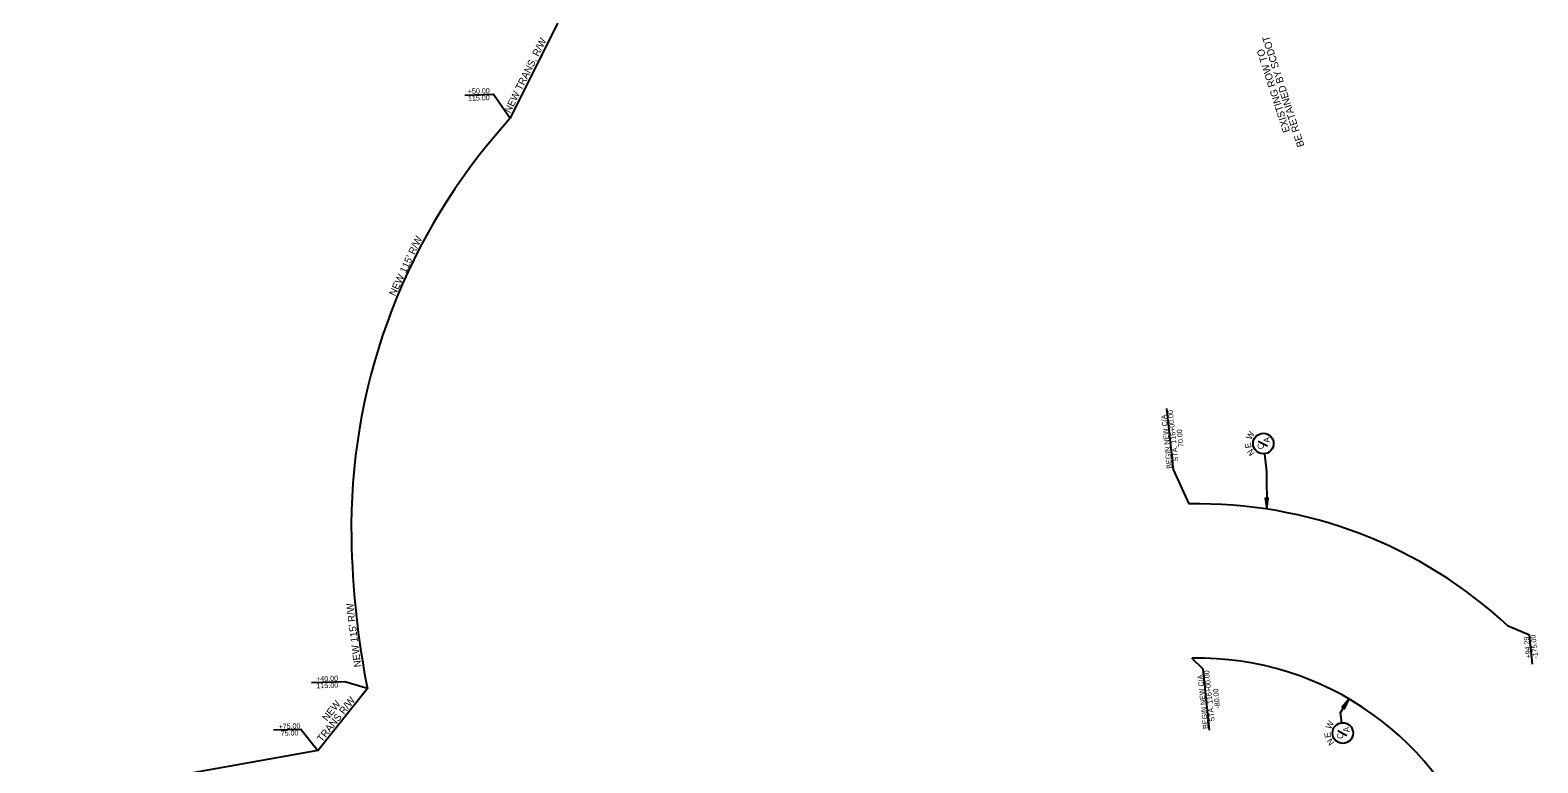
# Model space of a CAD drawing. Extents: x 2003184 to 2010449, y 855784 to 861212.
# Drawn here: x 2003206 to 2004672, y 858179 to 858891 of the extents above; entities that cross this region are included whole.
import ezdxf

# ---------------------------------------------------------------- set-up
doc = ezdxf.new("R2010")
doc.units = 0
for name, color, linetype in [('RD_PD_Control_Access', 7, 'Continuous'), ('RD_PD_RW', 7, 'Continuous'), ('RD_PD_RW_TX', 7, 'Continuous')]:
    doc.layers.add(name, color=color, linetype=linetype)

msp = doc.modelspace()

# ---------------------------------------------------------------- linework, layer by layer
at = {"layer": 'RD_PD_Control_Access'}
for p, q in [((2004399.8, 858491.4), (2004408.7, 858486.7)), ((2004477.1, 858210), (2004486, 858205.3))]:
    msp.add_line(p, q, dxfattribs=at)
for points in [[(2004405.9, 858479), (2004407.7, 858461.5), (2004408, 858425.3)], [(2004481, 858217.5), (2004479.9, 858227.7), (2004488.1, 858240.8)]]:
    msp.add_lwpolyline(points, dxfattribs=at)
for points in [[(2004408, 858425.3), (2004409.4, 858435.7), (2004407.9, 858434.1), (2004406.4, 858435.7)], [(2004488.1, 858240.8), (2004481.3, 858232.7), (2004483.4, 858233.3), (2004483.8, 858231.2)]]:
    msp.add_lwpolyline(points, close=True, dxfattribs=at)
for centre in [(2004404.8, 858488.9), (2004482, 858207.6)]:
    msp.add_circle(centre, 10, dxfattribs=at)
for radius, start in [(441, 46.9147), (291, 17.9087)]:
    msp.add_arc((2004341.6, 857989.3), radius, start, 91.2081, dxfattribs=at)
at = {"layer": 'RD_PD_RW'}
for p, q in [((2003718.9, 858897.4), (2003672.9, 858805.1)), ((2003672.9, 858805.1), (2003659.8, 858789.9)), ((2003485.9, 858190.6), (2003534.1, 858251.1)), ((2003485.9, 858190.6), (2003206.3, 858140.9))]:
    msp.add_line(p, q, dxfattribs=at)
for centre, radius, start, end in [((2004107.4, 858407.1), 589, 139.458, 181.0003), ((2004344.4, 858411.2), 826, 181.0003, 191.1779)]:
    msp.add_arc(centre, radius, start, end, dxfattribs=at)
at = {"layer": 'RD_PD_RW_TX'}
for points in [[(2003628.6, 858827.6), (2003656.6, 858828.4), (2003672.9, 858805.1)], [(2004310.6, 858523), (2004317, 858463.8), (2004332.3, 858430.2)], [(2004666.5, 858274.5), (2004663.5, 858302.8), (2004642.8, 858311.4)], [(2004352.6, 858210.3), (2004346.2, 858269.7), (2004335.4, 858280.3)], [(2003479.6, 858256.8), (2003512.2, 858257.8), (2003534.1, 858251.1)], [(2003442.8, 858210.6), (2003469.2, 858211.3), (2003485.9, 858190.6)]]:
    msp.add_lwpolyline(points, dxfattribs=at)

# ---------------------------------------------------------------- texts
at = {"layer": 'RD_PD_Control_Access'}
for s, height, rotation, p in [('STA. 116+00.00', 5, 96.1251, (2004322.1, 858471.9)), ('BEGIN NEW C/A', 5, 96.1251, (2004316, 858464.7)), ('70.00', 5, 96.1251, (2004327.3, 858485.8)), ('E', 6, 100.3188, (2004393.4, 858484.9)), ('W', 6, 62.6413, (2004393, 858492.1)), ('C', 6, 96.1251, (2004405.5, 858483.7)), ('A', 6, 96.1251, (2004411.3, 858490)), ('N', 6, 125.4371, (2004396.8, 858479.6)), ('+94.29', 5, 96.1251, (2004665, 858280.4)), ('-175.00', 5, 96.1251, (2004671.8, 858280.2)), ('BEGIN NEW C/A', 5, 96.1251, (2004351.3, 858211.9)), ('STA. 116+00.00', 5, 96.1251, (2004357.4, 858219)), ('-80.00', 5, 96.1251, (2004362.8, 858231.6)), ('W', 6, 62.6413, (2004470.3, 858210.8)), ('A', 6, 96.1251, (2004488.6, 858208.6)), ('E', 6, 100.3188, (2004470.7, 858203.6)), ('N', 6, 125.4371, (2004474, 858198.3)), ('C', 6, 96.1251, (2004482.8, 858202.3))]:
    msp.add_text(s, height=height, rotation=rotation, dxfattribs=at).set_placement(p)
at = {"layer": 'RD_PD_RW_TX'}
for s, height, rotation, p in [('NEW TRANS. R/W', 7, 63.4942, (2003672.8, 858809.5)), ('EXISTING ROW TO', 7, 107.8087, (2004430.8, 858792.4)), ('BE RETAINED BY SCDOT', 7, 107.8087, (2004444.7, 858778.3)), ('+50.00', 5, 1.6093, (2003631.7, 858828.8)), ('115.00', 5, 1.6093, (2003631.9, 858822)), ("NEW 115' R/W", 7, 64.9169, (2003561, 858631.7)), ("NEW 115' R/W", 7, 97.2483, (2003528.1, 858272)), ('+40.00', 5, 1.6093, (2003484.3, 858257.8)), ('115.00', 5, 1.6093, (2003484.6, 858251.1)), ('TRANS R/W', 7, 51.462, (2003489.9, 858198.3)), ('NEW', 7, 51.462, (2003494.9, 858218.6)), ('+75.00', 5, 1.6093, (2003447.7, 858211.6)), ('75.00', 5, 1.6093, (2003449.8, 858204.9))]:
    msp.add_text(s, height=height, rotation=rotation, dxfattribs=at).set_placement(p)

doc.saveas('drawing.dxf')
